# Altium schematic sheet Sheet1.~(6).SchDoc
size A; SheetNumber: 1; SheetTotal: 1
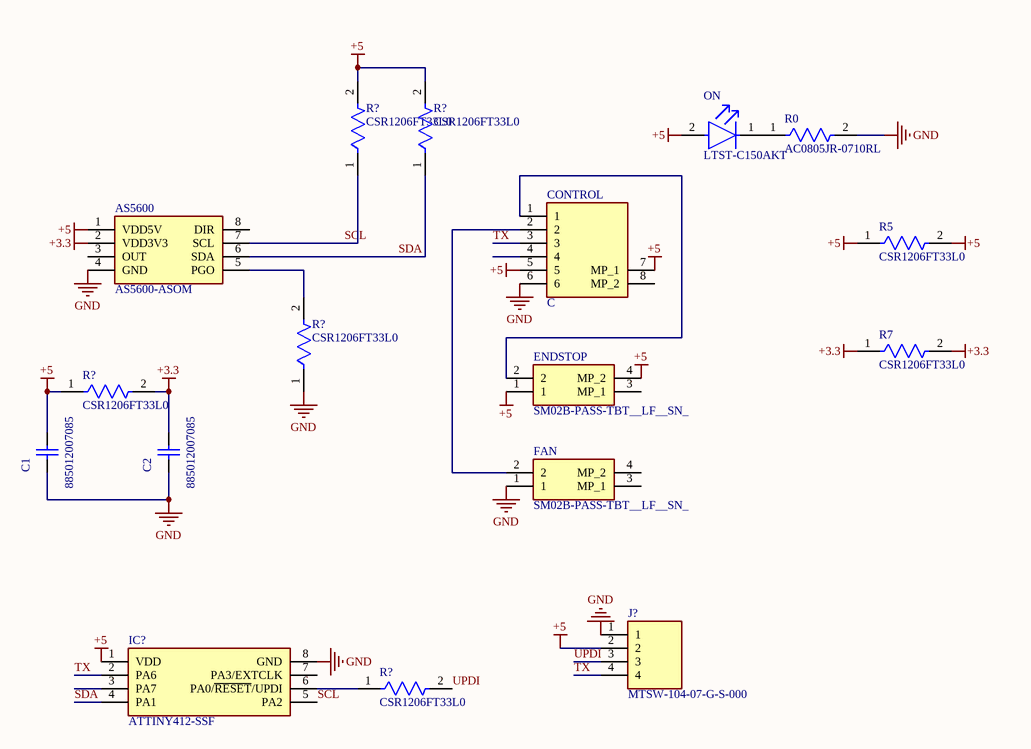
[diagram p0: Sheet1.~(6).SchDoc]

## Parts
(Parts that share a designator on the sheet are numbered #1, #2 ... from top to bottom, then left to right.)
AS5600  AS5600-ASOM  [SOIC127P600X175-8N]
C1  885012007085  [WCAP-CSGP_0805_L2W1.25H0.6_Reflow]
C2  885012007085  [WCAP-CSGP_0805_L2W1.25H0.6_Reflow]
CONTROL  C  [SM06BZESSTBLFSN]
ENDSTOP  SM02B-PASS-TBT__LF__SN_  [SM02BPASSTBTLFSN]
FAN  SM02B-PASS-TBT__LF__SN_  [SM02BPASSTBTLFSN]
IC?  ATTINY412-SSF  [SOIC127P600X175-8N]
J?  MTSW-104-07-G-S-000  [HDRV4W64P0X254_1X4_1016X254X864P]
ON  LTST-C150AKT  [FP-LTST-C150AKT-MFG]
R0  AC0805JR-0710RL  [FP-AC0805-MFG]
R5  CSR1206FT33L0  [FP-CSR1206-MFG]
R7  CSR1206FT33L0  [FP-CSR1206-MFG]
R?#1  CSR1206FT33L0  [FP-CSR1206-MFG]
R?#2  CSR1206FT33L0  [FP-CSR1206-MFG]
R?#3  CSR1206FT33L0  [FP-CSR1206-MFG]
R?#4  CSR1206FT33L0  [FP-CSR1206-MFG]
R?#5  CSR1206FT33L0  [FP-CSR1206-MFG]

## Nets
+3.3: AS5600.2(VDD3V3) C2.2 R7.1 R7.2 R?#3.2
+5: AS5600.1(VDD5V) C1.2 CONTROL.5 CONTROL.7(MP_1) ENDSTOP.1 ENDSTOP.4(MP_2) IC?.1(VDD) J?.2 ON.2(A) R5.1 R5.2 R?#1.2 R?#2.2 R?#3.1
GND: AS5600.4(GND) C1.1 C2.1 CONTROL.6 FAN.1 IC?.8(GND) J?.1 R0.2 R?#4.1
SCL: AS5600.7(SCL) IC?.5(PA2) R?#1.1
SDA: AS5600.6(SDA) IC?.4(PA1) R?#2.1
TX: CONTROL.3 IC?.2(PA6) J?.4
UPDI: J?.3 R?#5.2
NetAS5600_5: AS5600.5(PGO) R?#4.2
NetCONTROL_1: CONTROL.1 ENDSTOP.2
NetCONTROL_2: CONTROL.2 FAN.2
NetIC?_6: IC?.6(PA0/~{RESET}/UPDI) R?#5.1
NetON_1: ON.1(C) R0.1

Not connected (* = marked no-connect by the designer): AS5600 3(OUT) 8(DIR); CONTROL 4 8(MP_2); ENDSTOP 3(MP_1); FAN 3(MP_1) 4(MP_2); IC? 3(PA7) 7(PA3/EXTCLK)

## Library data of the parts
AS5600 = AS5600-ASOM: Integrated Circuit; Manufacturer_Name: ams OSRAM
C1 C2 = CMP-03913-89205616-2: Cap, Mlcc, 330PF, 100V, C0G/NP0, 0805;; Insulation Resistance: 10GΩ
CONTROL = SM06B-ZESS-TB_LF__SN_: Connector; Manufacturer_Name: JST (JAPAN SOLDERLESS TERMINALS); Manufacturer_Part_Number: SM06B-ZESS-TB(LF)(SN)
ENDSTOP FAN = SM02B-PASS-TBT__LF__SN_: Connector; Manufacturer_Name: JST (JAPAN SOLDERLESS TERMINALS); Manufacturer_Part_Number: SM02B-PASS-TBT (LF)(SN)
IC? = ATTINY412-SSF: Integrated Circuit; Manufacturer_Name: Microchip
J? = MTSW-104-07-G-S-000: Connector; Manufacturer_Name: SAMTEC
ON = CMP-22017-000004-1: LED AMBER CLEAR SMD; Manufacturer: Lite-On; Luminous Intensity: 6mcd; Viewing Angle: 130°; Wavelength: 602nm; Reverse Voltage: 5V; Forward Current: 30mA; Led Orientation: Top View; Power Dissipation: 100mW; Peak Emmision Wavelength: 610nm; Forward Voltage: 2.1V
R0 = CMP-03412-037687-1: RES SMD 10 OHM 5% 1/8W 0805; Manufacturer: Yageo; Automotive Grade: Grade 0; Value: 10Ω; Voltage Rating: 150V; Tolerance: 0.05
R5 R7 R?#1-R?#5 = CMP-26527-002831-1: General Purpose Thick Film Chip Resistor, 1206, 33mΩ, 1%, 0.5W; Resistance: 33mR; Temperature Coefficient: 100ppm/°C; Max Power Dissipation: 500mW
